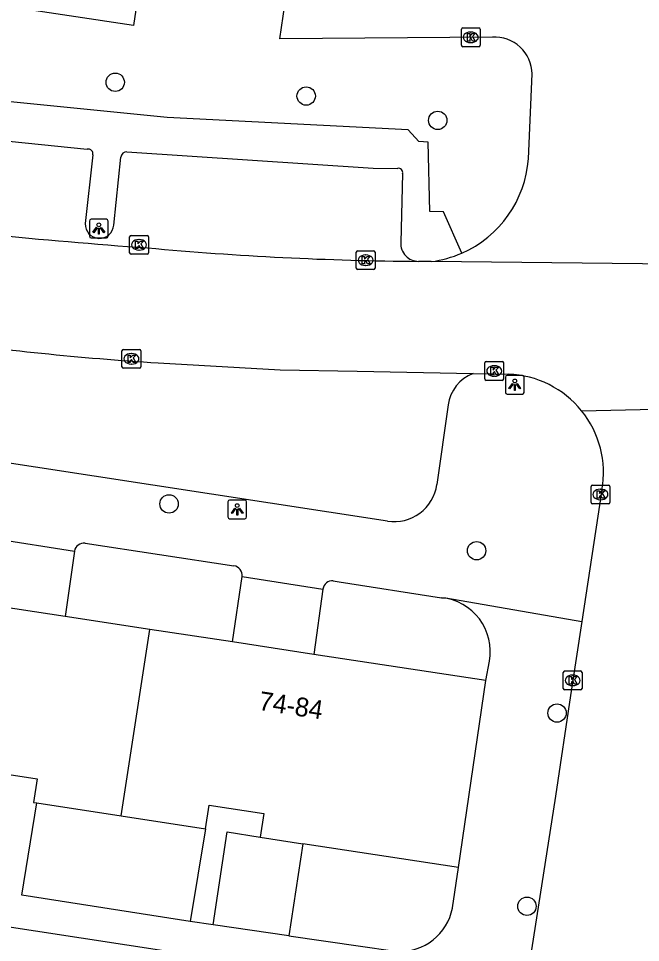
# Model space of a CAD drawing. Extents: x 161084 to 161928, y 385355 to 386522.
# Drawn here: x 161721.06 to 161754.18, y 385605.07 to 385654.26 of the extents above; entities that cross this region are included whole.
import ezdxf

# ---------------------------------------------------------------- set-up
doc = ezdxf.new("R2010")
doc.units = 0
for name, color, linetype in [('IMGEO_Boom', 7, 'Continuous'), ('IMGEO_Groenvoorziening', 7, 'Continuous'), ('IMGEO_Kolk', 7, 'Continuous'), ('IMGEO_Lichtpunt', 7, 'Continuous'), ('IMGEO_Pand', 7, 'Continuous'), ('IMGEO_Pand_nummerreeks', 7, 'Continuous'), ('IMGEO_Rijbaan_lokaal_open', 7, 'Continuous'), ('IMGEO_Voetpad_open', 7, 'Continuous')]:
    doc.layers.add(name, color=color, linetype=linetype)

msp = doc.modelspace()

# ---------------------------------------------------------------- linework, layer by layer
at = {"layer": 'IMGEO_Boom'}
for centre in [(161726.208, 385650.868), (161736.378, 385650.135), (161743.386, 385648.84), (161729.079, 385628.421), (161745.453, 385625.929), (161749.736, 385617.286), (161748.133, 385606.997)]:
    msp.add_circle(centre, 0.489, dxfattribs=at)
at = {"layer": 'IMGEO_Groenvoorziening'}
msp.add_lwpolyline([(161736.201, 385610.325), (161735.459, 385605.43)], dxfattribs=at)
at = {"layer": 'IMGEO_Kolk'}
for p, q in [((161744.641, 385652.836), (161744.641, 385653.688)), ((161744.716, 385653.762), (161745.568, 385653.762)), ((161745.642, 385653.688), (161745.642, 385652.836)), ((161745.129, 385653.542), (161745.154, 385653.542)), ((161745.568, 385652.762), (161744.716, 385652.762)), ((161745.152, 385652.982), (161745.127, 385652.982)), ((161726.976, 385641.79), (161726.976, 385642.642)), ((161727.051, 385642.716), (161727.903, 385642.716)), ((161727.464, 385642.496), (161727.489, 385642.496)), ((161727.977, 385642.642), (161727.977, 385641.79)), ((161727.487, 385641.936), (161727.462, 385641.936)), ((161739.044, 385640.967), (161739.044, 385641.819)), ((161739.119, 385641.893), (161739.971, 385641.893)), ((161740.045, 385641.819), (161740.045, 385640.967)), ((161727.903, 385641.716), (161727.051, 385641.716)), ((161739.532, 385641.673), (161739.557, 385641.673)), ((161739.971, 385640.893), (161739.119, 385640.893)), ((161739.555, 385641.113), (161739.53, 385641.113)), ((161726.569, 385635.719), (161726.569, 385636.571)), ((161726.644, 385636.645), (161727.496, 385636.645)), ((161727.057, 385636.425), (161727.082, 385636.425)), ((161727.57, 385636.571), (161727.57, 385635.719)), ((161745.894, 385635.071), (161745.894, 385635.923)), ((161745.969, 385635.997), (161746.821, 385635.997)), ((161746.895, 385635.923), (161746.895, 385635.071)), ((161727.496, 385635.645), (161726.644, 385635.645)), ((161727.08, 385635.865), (161727.055, 385635.865)), ((161746.382, 385635.777), (161746.407, 385635.777)), ((161746.821, 385634.997), (161745.969, 385634.997)), ((161746.405, 385635.217), (161746.38, 385635.217)), ((161751.548, 385628.496), (161751.548, 385629.348)), ((161751.623, 385629.422), (161752.475, 385629.422)), ((161752.036, 385629.202), (161752.061, 385629.202)), ((161752.549, 385629.348), (161752.549, 385628.496)), ((161752.059, 385628.642), (161752.034, 385628.642)), ((161752.475, 385628.422), (161751.623, 385628.422)), ((161750.068, 385618.597), (161750.068, 385619.449)), ((161750.143, 385619.523), (161750.995, 385619.523)), ((161750.556, 385619.303), (161750.581, 385619.303)), ((161751.069, 385619.449), (161751.069, 385618.597)), ((161750.579, 385618.743), (161750.554, 385618.743)), ((161750.995, 385618.523), (161750.143, 385618.523))]:
    msp.add_line(p, q, dxfattribs=at)
for points in [[(161744.641, 385652.836), (161744.641, 385653.688)], [(161744.716, 385653.762), (161745.568, 385653.762)], [(161745.642, 385653.688), (161745.642, 385652.836)], [(161744.962, 385653.462), (161745.085, 385653.462), (161745.085, 385653.311), (161745.215, 385653.462), (161745.379, 385653.462), (161745.233, 385653.311), (161745.386, 385653.062), (161745.234, 385653.062), (161745.149, 385653.226), (161745.085, 385653.159), (161745.085, 385653.062), (161744.962, 385653.062), (161744.962, 385653.462)], [(161745.568, 385652.762), (161744.716, 385652.762)], [(161726.976, 385641.79), (161726.976, 385642.642)], [(161727.051, 385642.716), (161727.903, 385642.716)], [(161727.297, 385642.416), (161727.42, 385642.416), (161727.42, 385642.265), (161727.55, 385642.416), (161727.714, 385642.416), (161727.568, 385642.265), (161727.721, 385642.016), (161727.569, 385642.016), (161727.484, 385642.18), (161727.42, 385642.113), (161727.42, 385642.016), (161727.297, 385642.016), (161727.297, 385642.416)], [(161727.977, 385642.642), (161727.977, 385641.79)], [(161739.044, 385640.967), (161739.044, 385641.819)], [(161739.119, 385641.893), (161739.971, 385641.893)], [(161740.045, 385641.819), (161740.045, 385640.967)], [(161727.903, 385641.716), (161727.051, 385641.716)], [(161739.365, 385641.593), (161739.488, 385641.593), (161739.488, 385641.442), (161739.618, 385641.593), (161739.782, 385641.593), (161739.636, 385641.442), (161739.789, 385641.193), (161739.637, 385641.193), (161739.552, 385641.357), (161739.488, 385641.29), (161739.488, 385641.193), (161739.365, 385641.193), (161739.365, 385641.593)], [(161739.971, 385640.893), (161739.119, 385640.893)], [(161726.569, 385635.719), (161726.569, 385636.571)], [(161726.644, 385636.645), (161727.496, 385636.645)], [(161727.57, 385636.571), (161727.57, 385635.719)], [(161726.89, 385636.345), (161727.013, 385636.345), (161727.013, 385636.194), (161727.143, 385636.345), (161727.307, 385636.345), (161727.161, 385636.194), (161727.314, 385635.945), (161727.162, 385635.945), (161727.077, 385636.109), (161727.013, 385636.042), (161727.013, 385635.945), (161726.89, 385635.945), (161726.89, 385636.345)], [(161745.894, 385635.071), (161745.894, 385635.923)], [(161745.969, 385635.997), (161746.821, 385635.997)], [(161746.895, 385635.923), (161746.895, 385635.071)], [(161727.496, 385635.645), (161726.644, 385635.645)], [(161746.215, 385635.697), (161746.338, 385635.697), (161746.338, 385635.546), (161746.468, 385635.697), (161746.632, 385635.697), (161746.486, 385635.546), (161746.639, 385635.297), (161746.487, 385635.297), (161746.402, 385635.461), (161746.338, 385635.394), (161746.338, 385635.297), (161746.215, 385635.297), (161746.215, 385635.697)], [(161746.821, 385634.997), (161745.969, 385634.997)], [(161751.548, 385628.496), (161751.548, 385629.348)], [(161751.623, 385629.422), (161752.475, 385629.422)], [(161751.869, 385629.122), (161751.992, 385629.122), (161751.992, 385628.971), (161752.122, 385629.122), (161752.286, 385629.122), (161752.14, 385628.971), (161752.293, 385628.722), (161752.141, 385628.722), (161752.056, 385628.886), (161751.992, 385628.819), (161751.992, 385628.722), (161751.869, 385628.722), (161751.869, 385629.122)], [(161752.549, 385629.348), (161752.549, 385628.496)], [(161752.475, 385628.422), (161751.623, 385628.422)], [(161750.068, 385618.597), (161750.068, 385619.449)], [(161750.143, 385619.523), (161750.995, 385619.523)], [(161750.389, 385619.223), (161750.512, 385619.223), (161750.512, 385619.072), (161750.642, 385619.223), (161750.806, 385619.223), (161750.66, 385619.072), (161750.813, 385618.823), (161750.661, 385618.823), (161750.576, 385618.987), (161750.512, 385618.92), (161750.512, 385618.823), (161750.389, 385618.823), (161750.389, 385619.223)], [(161751.069, 385619.449), (161751.069, 385618.597)], [(161750.995, 385618.523), (161750.143, 385618.523)]]:
    msp.add_lwpolyline(points, dxfattribs=at)
for centre, start, end in [((161744.718, 385653.686), 91.552, 178.448), ((161744.718, 385653.686), 91.552, 178.448), ((161745.566, 385653.686), 1.552, 88.448), ((161745.566, 385653.686), 1.552, 88.448), ((161744.718, 385652.838), 181.552, 268.448), ((161744.718, 385652.838), 181.552, 268.448), ((161745.566, 385652.838), 271.552, 358.448), ((161745.566, 385652.838), 271.552, 358.448), ((161727.053, 385642.64), 91.552, 178.448), ((161727.053, 385642.64), 91.552, 178.448), ((161727.901, 385642.64), 1.552, 88.448), ((161727.901, 385642.64), 1.552, 88.448), ((161739.121, 385641.817), 91.552, 178.448), ((161739.121, 385641.817), 91.552, 178.448), ((161739.969, 385641.817), 1.552, 88.448), ((161739.969, 385641.817), 1.552, 88.448), ((161727.053, 385641.792), 181.552, 268.448), ((161727.053, 385641.792), 181.552, 268.448), ((161727.901, 385641.792), 271.552, 358.448), ((161727.901, 385641.792), 271.552, 358.448), ((161739.121, 385640.969), 181.552, 268.448), ((161739.121, 385640.969), 181.552, 268.448), ((161739.969, 385640.969), 271.552, 358.448), ((161739.969, 385640.969), 271.552, 358.448), ((161726.646, 385636.569), 91.552, 178.448), ((161726.646, 385636.569), 91.552, 178.448), ((161727.494, 385636.569), 1.552, 88.448), ((161727.494, 385636.569), 1.552, 88.448), ((161745.971, 385635.921), 91.552, 178.448), ((161745.971, 385635.921), 91.552, 178.448), ((161746.819, 385635.921), 1.552, 88.448), ((161746.819, 385635.921), 1.552, 88.448), ((161726.646, 385635.721), 181.552, 268.448), ((161726.646, 385635.721), 181.552, 268.448), ((161727.494, 385635.721), 271.552, 358.448), ((161727.494, 385635.721), 271.552, 358.448), ((161745.971, 385635.073), 181.552, 268.448), ((161745.971, 385635.073), 181.552, 268.448), ((161746.819, 385635.073), 271.552, 358.448), ((161746.819, 385635.073), 271.552, 358.448), ((161751.625, 385629.346), 91.552, 178.448), ((161751.625, 385629.346), 91.552, 178.448), ((161752.473, 385629.346), 1.552, 88.448), ((161752.473, 385629.346), 1.552, 88.448), ((161751.625, 385628.498), 181.552, 268.448), ((161751.625, 385628.498), 181.552, 268.448), ((161752.473, 385628.498), 271.552, 358.448), ((161752.473, 385628.498), 271.552, 358.448), ((161750.145, 385619.447), 91.552, 178.448), ((161750.145, 385619.447), 91.552, 178.448), ((161750.993, 385619.447), 1.552, 88.448), ((161750.993, 385619.447), 1.552, 88.448), ((161750.145, 385618.599), 181.552, 268.448), ((161750.145, 385618.599), 181.552, 268.448), ((161750.993, 385618.599), 271.552, 358.448), ((161750.993, 385618.599), 271.552, 358.448)]:
    msp.add_arc(centre, 0.0765, start, end, dxfattribs=at)
for centre, major_axis, ratio, start_param, end_param in [((161745.128, 385653.262), (-0.387, 0.002), 0.722429, 4.712389, 7.853982), ((161745.153, 385653.262), (-0.39, 0.002), 0.717154, 1.570796, 4.712389), ((161727.463, 385642.216), (-0.387, 0.002), 0.722429, 4.712389, 7.853982), ((161727.488, 385642.216), (-0.39, 0.002), 0.717154, 1.570796, 4.712389), ((161739.531, 385641.393), (-0.387, 0.002), 0.722429, 4.712389, 7.853982), ((161739.556, 385641.393), (-0.39, 0.002), 0.717154, 1.570796, 4.712389), ((161727.056, 385636.145), (-0.387, 0.002), 0.722429, 4.712389, 7.853982), ((161727.081, 385636.145), (-0.39, 0.002), 0.717154, 1.570796, 4.712389), ((161746.381, 385635.497), (-0.387, 0.002), 0.722429, 4.712389, 7.853982), ((161746.406, 385635.497), (-0.39, 0.002), 0.717154, 1.570796, 4.712389), ((161752.035, 385628.922), (-0.387, 0.002), 0.722429, 4.712389, 7.853982), ((161752.06, 385628.922), (-0.39, 0.002), 0.717154, 1.570796, 4.712389), ((161750.555, 385619.023), (-0.387, 0.002), 0.722429, 4.712389, 7.853982), ((161750.58, 385619.023), (-0.39, 0.002), 0.717154, 1.570796, 4.712389)]:
    msp.add_ellipse(centre, major_axis=major_axis, ratio=ratio, start_param=start_param, end_param=end_param, dxfattribs=at)
at = {"layer": 'IMGEO_Lichtpunt'}
for p, q in [((161724.837, 385643.481), (161724.837, 385642.674)), ((161724.837, 385643.481), (161724.837, 385642.674)), ((161725.739, 385643.576), (161724.931, 385643.576)), ((161725.739, 385643.576), (161724.931, 385643.576)), ((161725.833, 385642.674), (161725.833, 385643.481)), ((161725.833, 385642.674), (161725.833, 385643.481)), ((161724.931, 385642.58), (161725.739, 385642.58)), ((161724.931, 385642.58), (161725.739, 385642.58)), ((161746.988, 385635.166), (161746.988, 385634.359)), ((161746.988, 385635.166), (161746.988, 385634.359)), ((161747.89, 385635.261), (161747.082, 385635.261)), ((161747.89, 385635.261), (161747.082, 385635.261)), ((161747.984, 385634.359), (161747.984, 385635.166)), ((161747.984, 385634.359), (161747.984, 385635.166)), ((161747.082, 385634.265), (161747.89, 385634.265)), ((161747.082, 385634.265), (161747.89, 385634.265)), ((161732.209, 385628.532), (161732.209, 385627.725)), ((161732.209, 385628.532), (161732.209, 385627.725)), ((161733.111, 385628.627), (161732.303, 385628.627)), ((161733.111, 385628.627), (161732.303, 385628.627)), ((161733.205, 385627.725), (161733.205, 385628.532)), ((161733.205, 385627.725), (161733.205, 385628.532)), ((161732.303, 385627.631), (161733.111, 385627.631)), ((161732.303, 385627.631), (161733.111, 385627.631))]:
    msp.add_line(p, q, dxfattribs=at)
for points in [[(161725.211, 385643.145), (161725.25, 385643.117), (161725.062, 385642.855), (161725.024, 385642.882), (161725.211, 385643.145)], [(161725.313, 385643.097), (161725.36, 385643.097), (161725.36, 385642.775), (161725.313, 385642.775), (161725.313, 385643.097)], [(161725.423, 385643.117), (161725.461, 385643.144), (161725.648, 385642.882), (161725.609, 385642.854), (161725.423, 385643.117)], [(161747.362, 385634.83), (161747.401, 385634.802), (161747.213, 385634.54), (161747.175, 385634.567), (161747.362, 385634.83)], [(161747.464, 385634.782), (161747.511, 385634.782), (161747.511, 385634.46), (161747.464, 385634.46), (161747.464, 385634.782)], [(161747.574, 385634.802), (161747.612, 385634.829), (161747.799, 385634.567), (161747.76, 385634.539), (161747.574, 385634.802)], [(161732.583, 385628.196), (161732.622, 385628.168), (161732.434, 385627.906), (161732.396, 385627.933), (161732.583, 385628.196)], [(161732.685, 385628.148), (161732.732, 385628.148), (161732.732, 385627.826), (161732.685, 385627.826), (161732.685, 385628.148)], [(161732.795, 385628.168), (161732.833, 385628.195), (161733.02, 385627.933), (161732.981, 385627.905), (161732.795, 385628.168)]]:
    msp.add_lwpolyline(points, dxfattribs=at)
for centre in [(161725.336, 385643.279), (161747.487, 385634.964), (161732.708, 385628.33)]:
    msp.add_circle(centre, 0.0994, dxfattribs=at)
for centre, start, end in [((161724.931, 385643.481), 90, 180), ((161724.931, 385643.481), 90, 180), ((161725.739, 385643.481), 0, 90), ((161725.739, 385643.481), 0, 90), ((161724.931, 385642.674), 180, 270), ((161724.931, 385642.674), 180, 270), ((161725.739, 385642.674), 270, 0), ((161725.739, 385642.674), 270, 360), ((161747.082, 385635.166), 90, 180), ((161747.082, 385635.166), 90, 180), ((161747.89, 385635.166), 0, 90), ((161747.89, 385635.166), 0, 90), ((161747.082, 385634.359), 180, 270), ((161747.082, 385634.359), 180, 270), ((161747.89, 385634.359), 270, 0), ((161747.89, 385634.359), 270, 360), ((161732.303, 385628.532), 90, 180), ((161732.303, 385628.532), 90, 180), ((161733.111, 385628.532), 0, 90), ((161733.111, 385628.532), 0, 90), ((161732.303, 385627.725), 180, 270), ((161732.303, 385627.725), 180, 270), ((161733.111, 385627.725), 270, 0), ((161733.111, 385627.725), 270, 360)]:
    msp.add_arc(centre, 0.0946, start, end, dxfattribs=at)
at = {"layer": 'IMGEO_Pand'}
for points in [[(161723.549, 385622.423), (161719.211, 385623.083)], [(161728.049, 385621.738), (161723.549, 385622.423)], [(161726.527, 385611.808), (161728.049, 385621.738)], [(161732.452, 385621.067), (161728.049, 385621.738)], [(161736.785, 385620.408), (161732.452, 385621.067)], [(161745.953, 385619.012), (161736.785, 385620.408)], [(161744.491, 385609.053), (161745.953, 385619.012)], [(161718.961, 385612.968), (161719.155, 385614.231), (161722.045, 385613.788), (161721.851, 385612.525), (161722.032, 385612.497)], [(161722.032, 385612.497), (161726.527, 385611.808)], [(161731.021, 385611.119), (161731.215, 385612.382), (161734.124, 385611.936), (161733.93, 385610.673)], [(161726.527, 385611.808), (161731.021, 385611.119)], [(161733.93, 385610.673), (161736.201, 385610.325)], [(161744.491, 385609.053), (161736.201, 385610.325)]]:
    msp.add_lwpolyline(points, dxfattribs=at)
at = {"layer": 'IMGEO_Rijbaan_lokaal_open'}
for points in [[(161746.296, 385653.272), (161734.97, 385653.181), (161735.33, 385655.62), (161727.616, 385656.762), (161727.186, 385653.884), (161714.168, 385655.862), (161713.594, 385652.48), (161709.775, 385653.114)], [(161748.212, 385646.795), (161748.414, 385651.31)], [(161743.038, 385641.32), (161742.367, 385641.332)], [(161759.599, 385641.031), (161754.282, 385641.202), (161743.038, 385641.32)], [(161728.498, 385635.926), (161734.991, 385635.562), (161739.101, 385635.482), (161745.271, 385635.362)], [(161745.271, 385635.362), (161746.396, 385635.341), (161747.153, 385635.326)], [(161751.044, 385633.38), (161761.205, 385633.614)], [(161752.13, 385629.167), (161751.053, 385622.152)], [(161751.053, 385622.152), (161750.449, 385618.218), (161749.647, 385612.852), (161748.381, 385604.68)]]:
    msp.add_lwpolyline(points, dxfattribs=at)
for centre, radius, start, end in [((161746.412, 385651.274), 2.002, 1.044, 93.3354), ((161742.277, 385647.22), 5.95, 293.6702, 355.9), ((161748.374, 385929.478), 288.153, 262.56679, 265.93045), ((161743.652, 385812.553), 171.226, 264.72985, 269.56988), ((161742.264, 385647.277), 6.007, 277.4004, 293.5679), ((161739.697, 385809.071), 173.507, 262.18177, 266.29917), ((161746.962, 385630.081), 5.248, 38.9421, 87.9161), ((161746.96, 385630.081), 5.25, 349.9775, 38.9319)]:
    msp.add_arc(centre, radius, start, end, dxfattribs=at)
at = {"layer": 'IMGEO_Voetpad_open'}
for points in [[(161744.666, 385641.771), (161743.694, 385643.971), (161742.967, 385643.984), (161742.868, 385647.674), (161742.386, 385647.712), (161741.816, 385648.343), (161728.98, 385648.987), (161712.28, 385650.66), (161707.348, 385651.572)], [(161711.344, 385648.748), (161713.233, 385648.48), (161724.722, 385647.3)], [(161725.012, 385647.005), (161724.612, 385643.345)], [(161726.135, 385643.26), (161726.502, 385646.884)], [(161726.831, 385647.171), (161739.945, 385646.291), (161741.243, 385646.284)], [(161741.514, 385646.007), (161741.412, 385642.334)], [(161743.934, 385633.686), (161743.338, 385629.452)], [(161740.712, 385627.499), (161703.201, 385633.251)], [(161719.738, 385626.581), (161724.038, 385625.907)], [(161724.601, 385626.328), (161732.527, 385625.122)], [(161724.038, 385625.907), (161723.549, 385622.423)], [(161732.452, 385621.067), (161732.966, 385624.551)], [(161732.966, 385624.551), (161737.273, 385623.887)], [(161737.819, 385624.321), (161738.133, 385624.272), (161743.587, 385623.423)], [(161737.273, 385623.887), (161736.785, 385620.408)], [(161743.587, 385623.423), (161743.814, 385623.414), (161751.053, 385622.152)], [(161745.953, 385619.012), (161746.133, 385620.045)], [(161730.197, 385606.186), (161721.233, 385607.593), (161722.032, 385612.497)], [(161731.021, 385611.119), (161730.197, 385606.186)], [(161731.425, 385606.015), (161732.178, 385610.956), (161733.93, 385610.673)], [(161739.275, 385604.876), (161740.99, 385604.627), (161741.242, 385604.603), (161741.495, 385604.601), (161741.748, 385604.622), (161741.997, 385604.665), (161742.242, 385604.731), (161742.479, 385604.818), (161742.708, 385604.926), (161742.927, 385605.054), (161743.133, 385605.201), (161743.325, 385605.366), (161743.502, 385605.547), (161743.662, 385605.743), (161743.803, 385605.953), (161743.925, 385606.175), (161744.027, 385606.407), (161744.108, 385606.647), (161744.167, 385606.893), (161744.173, 385606.922), (161744.491, 385609.053)], [(161714.658, 385606.809), (161736.552, 385603.449)], [(161731.425, 385606.015), (161730.197, 385606.186)], [(161735.459, 385605.43), (161731.425, 385606.015)], [(161735.459, 385605.43), (161739.275, 385604.876)]]:
    msp.add_lwpolyline(points, dxfattribs=at)
for centre, radius, start, end in [((161724.783, 385647.07), 0.238, 344.0339, 104.9867), ((161726.842, 385646.826), 0.345, 91.803, 170.396), ((161741.291, 385646.06), 0.229, 346.6536, 102.0918), ((161725.374, 385643.32), 0.763, 178.0993, 355.5119), ((161742.376, 385642.297), 0.965, 177.8088, 269.4396), ((161746.026, 385633.389), 2.113, 110.9325, 171.9065), ((161741.06, 385629.773), 2.3, 261.2912, 351.9864), ((161724.54, 385625.822), 0.509, 83.1576, 170.4192), ((161732.459, 385624.615), 0.511, 352.7869, 82.3211), ((161737.777, 385623.813), 0.509, 85.2851, 171.6753), ((161743.305, 385620.562), 2.875, 349.6426, 84.368)]:
    msp.add_arc(centre, radius, start, end, dxfattribs=at)

# ---------------------------------------------------------------- texts
at = {"layer": 'IMGEO_Pand_nummerreeks'}
msp.add_text('74-84', height=1, rotation=351.2832, dxfattribs=at).set_placement((161733.809, 385617.46))

doc.saveas('drawing.dxf')
